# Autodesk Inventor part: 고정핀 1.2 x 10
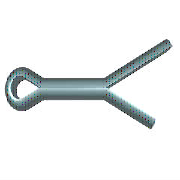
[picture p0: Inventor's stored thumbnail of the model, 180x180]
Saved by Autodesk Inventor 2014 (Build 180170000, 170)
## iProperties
IsCustomPart: 1
Created: 2012-02
Part Number: 고정핀 1.2 x 10
Material: 강철
Description: 분할 핀
Document SubType Name: Modeling
Standard: ISO 1234
Designer: test
Standard Revision: Second edition 1997-11-01
Standards Organization: ISO
Language: ko-KR
Size Designation: 1.2 x 10
Categories: <MemberInstance><Categories><Category DisplayName="조임쇠" InternalName="e4da775c-781d-43d5-af7c-5136215cf5a6" Mnemonic="FSTN"><Category DisplayName="핀" InternalNa
Density: 7.85 g/cm^3
Appearance: Steel
Author: test
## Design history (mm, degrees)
sketch "스케치1"
  geometry: L1 (0, 0.5)-(5, 0.5); L2 (0, -0.5)-(5, -0.5); L3 (5, 0.5)-(10, 2.416); L4 (10, 2.416)-(10.167, 1.98); L5 (10.167, 1.98)-(5, 0); L6 (5, 0)-(12.667, -2.937); L7 (12.667, -2.937)-(12.5, -3.373); L8 (12.5, -3.373)-(5, -0.5); L9 (0, 0)-(-1.875, -0.484); L10 (0, 0)-(-1.875, 0.484); L11 (0, 0.5)-(0, -0.5); L12 (0, 0.5)-(-1.742, 0.966); L13 (0, -0.5)-(-1.742, -0.966); L14 (-3, 0)-(5, 0); L15 (5, 0.5)-(5, -0.5); A1 r 1 centre (-2, 0) between (-1.742, 0.966) and (-1.742, -0.966); A2 r 0.5 centre (-2, 0) between (-1.875, 0.484) and (-1.875, -0.484); 1 further point
  constraints: 30 end point, 5 point on circle, 4 parallel, 4 perpendicular, 4 point on line, 4 tangent, 2 centre point, 2 midpoint, 1 coincident, 1 horizontal
  dimensions: "d0" = 5 distance of L1.start L1.end (= MSIAB); "d1" = 10 horizontal distance of L1.start L3.end (= SNLG); "d2" = 159.037 deg angle of L1 L3; "d3" = 159.037 deg angle of L2 L8; "d4" = 2.5 horizontal distance of L3.end L7.end (= LGDIF); "d5" = 0.5 radius of A2 (= -0.5 x SNND1 + 0.5 x KBR); "d6" = 1 radius of A1 (= 0.5 x KBR); "d7" = 0.5 distance from line of L1 L9.start (= 0.5 x SNND1); "d8" = 0.5 distance between parallel lines of L2 L14 (= 0.5 x SNND1); "d9" = 2 distance from line of L11 A1.centre (= KOL - 0.5 x KBR)
extrude "본체" new body sketch "스케치1" stored distance "d10" = 1 (= SNND1); taper "d11" = 0 deg
workaxis "Work Axis1"
workplane "Work Plane1"
body "Solid1"
fillet "모깎기" dims "d12" = 0.35 (= 0.35 x SNND1)
workplane "Work Plane3"
other parameters: "SNND" = 1.2 [user parameter], "SNLG" = 10 [user parameter; used in 1 equation term], "SNND1" = 1 [user parameter; used in 5 equation terms], "KBR" = 2 [user parameter; used in 3 equation terms], "KOL" = 3 [user parameter; used in 1 equation term], "LGDIF" = 2.5 [user parameter; used in 1 equation term], "MSIAB" = 5 [user parameter; used in 1 equation term], "d15" = 0, "d16" = 0, "d17" = 0, "NNDMAX" = 5.5 [user parameter], "DSH" = 2.6 [user parameter], "NNDMIN" = 4.5 [user parameter]
